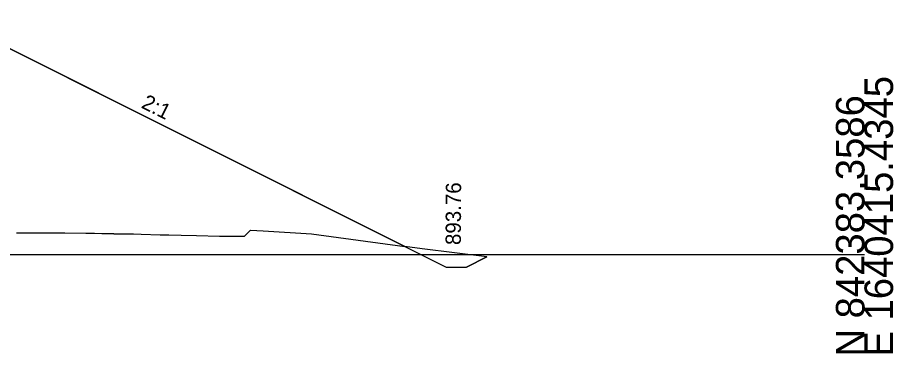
# Model space of a CAD drawing. Extents: x -26 to 1638757, y -10 to 843341.
# Drawn here: x 1267 to 1352.8, y 1990.3 to 2023.2 of the extents above; entities that cross this region are included whole.
import ezdxf

# ---------------------------------------------------------------- set-up
doc = ezdxf.new("R2010")
doc.units = 0
for name, color, linetype in [('Exist Cross Section Cell', 7, 'Continuous'), ('Exist XS Ground Line', 7, 'Continuous'), ('Prop CMT Slope Grass', 7, 'Continuous'), ('Prop XS DDE', 7, 'Continuous'), ('Prop XS SE Text', 7, 'Continuous'), ('Prop XS Side Slope Text', 7, 'Continuous'), ('Scratch_Level_2', 7, 'Continuous'), ('Scratch_Level_3', 7, 'Continuous')]:
    doc.layers.add(name, color=color, linetype=linetype)

msp = doc.modelspace()

# ---------------------------------------------------------------- linework, layer by layer
at = {"layer": 'Exist Cross Section Cell'}
msp.add_line((1150, 2000), (1350, 2000), dxfattribs=at)
at = {"layer": 'Exist XS Ground Line'}
msp.add_lwpolyline([(1266.905, 2002.129), (1268.292, 2002.136), (1270.072, 2002.138), (1271.001, 2002.134), (1271.668, 2002.125), (1273.711, 2002.087), (1274.573, 2002.075), (1275.273, 2002.061), (1276.405, 2002.042), (1276.42, 2002.042), (1276.46, 2002.041), (1276.556, 2002.04), (1278.371, 2002.01), (1279.13, 2001.997), (1280.977, 2001.941), (1281.839, 2001.92), (1283.041, 2001.894), (1284.549, 2001.87), (1286.81, 2001.813), (1287.463, 2001.794), (1289.094, 2001.803), (1289.249, 2001.803), (1289.32, 2001.873), (1289.848, 2002.389), (1291.087, 2002.314), (1295.821, 2002.028), (1304.97, 2000.785)], dxfattribs=at)
at = {"layer": 'Prop CMT Slope Grass'}
msp.add_lwpolyline([(1255.908, 2023.212), (1257.917, 2023.051), (1260.918, 2022.811), (1304.97, 2000.785)], dxfattribs=at)
at = {"layer": 'Prop XS DDE'}
for p, q in [((1304.97, 2000.785), (1309.015, 1998.762)), ((1313.013, 1999.761), (1311.015, 1998.762)), ((1309.015, 1998.762), (1311.015, 1998.762))]:
    msp.add_line(p, q, dxfattribs=at)
at = {"layer": 'Scratch_Level_2'}
for p, q in [((1306.652, 2000.557), (1304.97, 2000.785)), ((1304.97, 2000.785), (1309.015, 1998.762)), ((1313.013, 1999.761), (1306.652, 2000.557)), ((1311.015, 1998.762), (1313.013, 1999.761)), ((1309.015, 1998.762), (1311.015, 1998.762))]:
    msp.add_line(p, q, dxfattribs=at)
at = {"layer": 'Scratch_Level_3'}
msp.add_line((1304.97, 2000.785), (1264.847, 2020.847), dxfattribs=at)
msp.add_lwpolyline([(1266.905, 2002.129), (1268.292, 2002.136), (1270.072, 2002.138), (1271.001, 2002.134), (1271.668, 2002.125), (1273.711, 2002.087), (1274.573, 2002.075), (1275.273, 2002.061), (1276.405, 2002.042), (1276.42, 2002.042), (1276.46, 2002.041), (1276.556, 2002.04), (1278.371, 2002.01), (1279.13, 2001.997), (1280.977, 2001.941), (1281.839, 2001.92), (1283.041, 2001.894), (1284.549, 2001.87), (1286.81, 2001.813), (1287.463, 2001.794), (1289.094, 2001.803), (1289.249, 2001.803), (1289.32, 2001.873), (1289.848, 2002.389), (1291.087, 2002.314), (1295.821, 2002.028), (1304.97, 2000.785)], dxfattribs=at)

# ---------------------------------------------------------------- texts
at = {"layer": 'Exist Cross Section Cell'}
for s, p in [('E 1640415.4345', (1352.8, 1990)), ('N 842383.3586', (1350, 1990))]:
    msp.add_text(s, height=2.8, rotation=90, dxfattribs=at).set_placement(p)
at = {"layer": 'Prop XS SE Text'}
msp.add_text('893.76', height=1.5, rotation=89.68642, dxfattribs=at).set_placement((1310.45, 2000.928))
at = {"layer": 'Prop XS Side Slope Text'}
msp.add_text('2:1', height=1.5, rotation=333.40359, dxfattribs=at).set_placement((1279.057, 2014.414))

doc.saveas('drawing.dxf')
